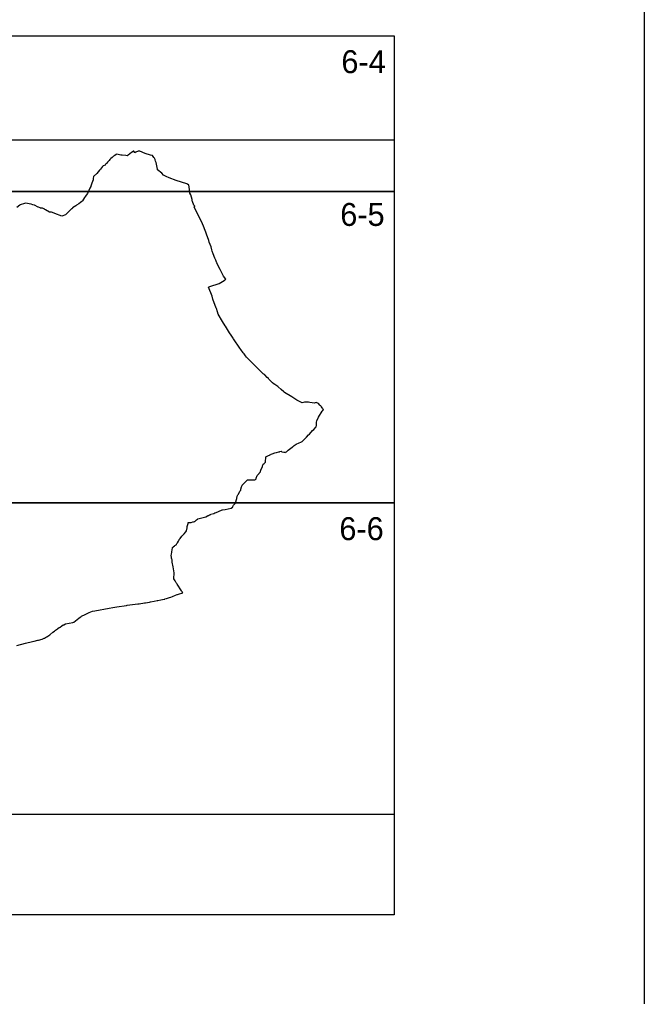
# Model space of a CAD drawing. Extents: x -447352 to -425530, y -1135906 to -1121091.
# Drawn here: x -429213.6 to -428963, y -1126703.7 to -1126311.8 of the extents above; entities that cross this region are included whole.
import ezdxf

# ---------------------------------------------------------------- set-up
doc = ezdxf.new("R2010")
doc.units = 0
for name, color, linetype in [('Vrstva 1', 7, 'Continuous'), ('Vrstva 10', 7, 'Continuous'), ('Vrstva 4', 7, 'Continuous')]:
    doc.layers.add(name, color=color, linetype=linetype)

msp = doc.modelspace()

# ---------------------------------------------------------------- linework, layer by layer
at = {"layer": 'Vrstva 1'}
msp.add_lwpolyline([(-430447.95, -1126056.63), (-430447.95, -1127106.63), (-428962.95, -1127106.63), (-428962.95, -1126056.63)], close=True, dxfattribs=at)
msp.add_lwpolyline([(-429214.66, -1126562.92), (-429211.12, -1126562.05), (-429208.35, -1126561.37), (-429207.68, -1126561.16), (-429206.19, -1126560.81), (-429205.98, -1126560.75), (-429204.55, -1126560.35), (-429203.95, -1126560.09), (-429203.73, -1126560), (-429203.57, -1126559.93), (-429202.75, -1126559.48), (-429202.69, -1126559.44), (-429201.38, -1126558.67), (-429200.23, -1126557.62), (-429199.58, -1126557.11), (-429199.45, -1126557), (-429199.43, -1126556.99), (-429199.27, -1126556.87), (-429199.12, -1126556.76), (-429198.32, -1126556.2), (-429198.26, -1126556.16), (-429198.19, -1126556.11), (-429197.68, -1126555.76), (-429197.31, -1126555.5), (-429196.65, -1126555.04), (-429196.06, -1126554.63), (-429195.9, -1126554.66), (-429195.89, -1126554.66), (-429195.87, -1126554.65), (-429195.14, -1126554.25), (-429192.18, -1126553.67), (-429191.76, -1126553.53), (-429189.73, -1126551.9), (-429189.26, -1126551.56), (-429189.23, -1126551.54), (-429188.87, -1126551.28), (-429188.69, -1126551.15), (-429187.3, -1126550.45), (-429185.89, -1126549.81), (-429185.59, -1126549.66), (-429184.33, -1126549.2), (-429183.33, -1126548.96), (-429177.62, -1126547.9), (-429176.2, -1126547.63), (-429174.49, -1126547.38), (-429170.62, -1126546.82), (-429170.38, -1126546.79), (-429166.08, -1126546.26), (-429165.55, -1126546.2), (-429163.4, -1126545.85), (-429163.08, -1126545.79), (-429161.42, -1126545.52), (-429161.02, -1126545.46), (-429159.61, -1126545.16), (-429158.32, -1126544.89), (-429158.11, -1126544.85), (-429156.94, -1126544.63), (-429156.27, -1126544.5), (-429156.25, -1126544.49), (-429155.34, -1126544.28), (-429155.27, -1126544.26), (-429154.62, -1126544.11), (-429154.27, -1126543.99), (-429153.38, -1126543.7), (-429152.94, -1126543.56), (-429152.29, -1126543.31), (-429152.17, -1126543.27), (-429151.08, -1126542.78), (-429151.08, -1126542.78), (-429150.96, -1126542.74), (-429150.31, -1126542.51), (-429150.22, -1126542.48), (-429149.79, -1126542.33), (-429148.13, -1126541.75), (-429148.15, -1126541.69), (-429148.26, -1126541.52), (-429148.42, -1126541.3), (-429148.64, -1126540.97), (-429150.34, -1126538.33), (-429150.55, -1126537.99), (-429150.72, -1126537.72), (-429151.16, -1126537), (-429151.69, -1126536.15), (-429151.53, -1126533.79), (-429151.52, -1126533.7), (-429151.91, -1126531.41), (-429151.91, -1126531.39), (-429151.92, -1126531.36), (-429151.92, -1126531.36), (-429151.92, -1126531.33), (-429152.33, -1126529.5), (-429152.34, -1126529.31), (-429152.4, -1126528.51), (-429152.5, -1126528.23), (-429152.51, -1126528.21), (-429152.62, -1126528), (-429152.66, -1126527.92), (-429152.67, -1126527.54), (-429152.7, -1126526.84), (-429152.65, -1126526.34), (-429152.65, -1126526.33), (-429152.56, -1126525.46), (-429152.54, -1126525.36), (-429152.25, -1126523.71), (-429152.17, -1126523.63), (-429151.87, -1126523.29), (-429151.81, -1126523.22), (-429151.55, -1126523.1), (-429151.49, -1126523.05), (-429151.23, -1126522.84), (-429151, -1126522.67), (-429150.79, -1126522.51), (-429150.73, -1126522.47), (-429150.65, -1126522.33), (-429150.57, -1126522.22), (-429150.46, -1126522.05), (-429150.24, -1126521.72), (-429149.82, -1126521.06), (-429149.69, -1126520.81), (-429149.68, -1126520.8), (-429149.54, -1126520.51), (-429149.49, -1126520.43), (-429149.31, -1126520.09), (-429149.17, -1126519.95), (-429148.87, -1126519.63), (-429148.7, -1126519.45), (-429148.42, -1126519.1), (-429148.29, -1126518.94), (-429147.6, -1126518.08), (-429146.94, -1126517.27), (-429146.65, -1126516.91), (-429146.41, -1126515.74), (-429146.35, -1126515.51), (-429146.28, -1126515.23), (-429145.96, -1126513.93), (-429145.88, -1126513.64), (-429145.88, -1126513.61), (-429145.86, -1126513.56), (-429145.7, -1126513.55), (-429145.68, -1126513.55), (-429145.44, -1126513.55), (-429144.75, -1126513.53), (-429144.74, -1126513.53), (-429144.71, -1126513.53), (-429144.03, -1126513.35), (-429143.83, -1126513.3), (-429143.41, -1126513.19), (-429143.39, -1126513.17), (-429143.33, -1126513.11), (-429143.03, -1126512.84), (-429142.91, -1126512.75), (-429142.57, -1126512.49), (-429142.15, -1126512.17), (-429142.08, -1126512.16), (-429141.52, -1126512), (-429138.82, -1126511.23), (-429138.23, -1126510.96), (-429137.9, -1126510.81), (-429137.85, -1126510.79), (-429137.75, -1126510.74), (-429137.39, -1126510.55), (-429137.34, -1126510.53), (-429137.31, -1126510.52), (-429137.3, -1126510.51), (-429137.27, -1126510.49), (-429136.96, -1126510.34), (-429136.9, -1126510.31), (-429136.79, -1126510.26), (-429135.71, -1126509.92), (-429135.28, -1126509.74), (-429134.76, -1126509.52), (-429133.75, -1126509.11), (-429132.33, -1126508.48), (-429132.19, -1126508.47), (-429131.06, -1126508.42), (-429128.66, -1126507.86), (-429128.13, -1126507.47), (-429128.06, -1126507.34), (-429127.97, -1126507.17), (-429127.71, -1126506.66), (-429127.36, -1126506.22), (-429127.34, -1126506.2), (-429127.13, -1126505.91), (-429127.02, -1126505.74), (-429127.01, -1126505.73), (-429126.47, -1126503.95), (-429126.46, -1126503.93), (-429126.26, -1126502.97), (-429126, -1126502.51), (-429125.81, -1126502.18), (-429125.26, -1126501.06), (-429124.88, -1126500.55), (-429124.85, -1126500.42), (-429124.78, -1126500.12), (-429124.75, -1126499.98), (-429124.69, -1126499.73), (-429124.67, -1126499.63), (-429124.35, -1126498.62), (-429124.34, -1126498.61), (-429124.05, -1126498.34), (-429123.39, -1126497.7), (-429123.34, -1126497.66), (-429122.87, -1126497.18), (-429122.61, -1126496.91), (-429122.51, -1126496.8), (-429122.14, -1126496.49), (-429122.1, -1126496.49), (-429122.09, -1126496.49), (-429121.68, -1126496.48), (-429121.51, -1126496.48), (-429120.88, -1126496.5), (-429120.17, -1126496.5), (-429119.2, -1126496.41), (-429119.17, -1126496.41), (-429118.92, -1126496.38), (-429118.7, -1126496.02), (-429118.65, -1126495.89), (-429118.63, -1126495.84), (-429118.61, -1126495.78), (-429118.25, -1126494.76), (-429118.11, -1126494.6), (-429118.01, -1126494.48), (-429117.97, -1126494.44), (-429117.91, -1126494.36), (-429117.79, -1126494.23), (-429117.52, -1126493.92), (-429117.43, -1126493.81), (-429117.33, -1126493.69), (-429116.99, -1126493.3), (-429116.92, -1126492.92), (-429116.86, -1126492.6), (-429116.79, -1126492.47), (-429116.24, -1126491.55), (-429116.13, -1126491.16), (-429115.94, -1126490.46), (-429115.82, -1126490.17), (-429115.53, -1126489.91), (-429114.98, -1126489.4), (-429114.91, -1126489.33), (-429114.81, -1126487.22), (-429113.79, -1126486.74), (-429113.39, -1126486.53), (-429113.14, -1126486.39), (-429112.85, -1126486.24), (-429112.63, -1126486.16), (-429112.29, -1126486.03), (-429112.24, -1126486.01), (-429111.15, -1126485.6), (-429111.14, -1126485.6), (-429110.65, -1126485.54), (-429110.57, -1126485.52), (-429109.54, -1126485.26), (-429109.39, -1126485.22), (-429109.3, -1126485.19), (-429109.13, -1126485.14), (-429108.6, -1126484.97), (-429108.6, -1126484.97), (-429108.59, -1126484.98), (-429108.59, -1126484.99), (-429108.56, -1126485.04), (-429108.43, -1126485.26), (-429107.55, -1126485.36), (-429107.35, -1126485.38), (-429106.99, -1126485.42), (-429106.9, -1126485.38), (-429106.47, -1126485.2), (-429105.82, -1126484.49), (-429104.18, -1126483.33), (-429104.09, -1126483.27), (-429103.92, -1126483.15), (-429103.41, -1126482.74), (-429102.66, -1126482.13), (-429101.39, -1126481.57), (-429100.77, -1126481.29), (-429100.23, -1126481.05), (-429100.17, -1126481.02), (-429098.52, -1126479.35), (-429097.68, -1126478.46), (-429097.32, -1126478.09), (-429096.13, -1126476.72), (-429095.53, -1126476.27), (-429095.48, -1126476.22), (-429094.64, -1126475.21), (-429094.44, -1126474.64), (-429094.53, -1126473.31), (-429094.31, -1126472.82), (-429093.67, -1126471.37), (-429092.21, -1126468.89), (-429092.18, -1126468.84), (-429092.18, -1126468.84), (-429092.16, -1126468.82), (-429092.13, -1126468.78), (-429091.98, -1126468.58), (-429091.72, -1126468.24), (-429091.98, -1126467.95), (-429092.12, -1126467.72), (-429092.59, -1126466.99), (-429092.79, -1126466.79), (-429092.94, -1126466.63), (-429093.13, -1126466.43), (-429093.71, -1126465.87), (-429094.56, -1126465.39), (-429095.01, -1126465.57), (-429095.34, -1126465.7), (-429097.09, -1126465.42), (-429097.7, -1126465.33), (-429097.84, -1126465.32), (-429098.43, -1126465.31), (-429098.81, -1126465.25), (-429098.97, -1126465.23), (-429099.01, -1126465.22), (-429099.04, -1126465.22), (-429099.04, -1126465.22), (-429099.07, -1126465.22), (-429099.17, -1126465.25), (-429099.3, -1126465.29), (-429100.2, -1126465.52), (-429100.27, -1126465.49), (-429102.34, -1126464.45), (-429104.36, -1126463.18), (-429107.27, -1126461.35), (-429107.43, -1126461.22), (-429107.47, -1126461.18), (-429107.56, -1126461.1), (-429108.7, -1126460.17), (-429109.85, -1126459.13), (-429109.96, -1126459.02), (-429111.17, -1126458.26), (-429111.45, -1126458.04), (-429112.08, -1126457.54), (-429112.39, -1126457.29), (-429112.89, -1126456.76), (-429113.61, -1126456), (-429113.76, -1126455.84), (-429114.22, -1126455.35), (-429115.19, -1126454.32), (-429115.39, -1126454.22), (-429115.39, -1126454.22), (-429115.57, -1126454.12), (-429115.77, -1126454.02), (-429116.6, -1126453.19), (-429117.23, -1126452.57), (-429118.41, -1126451.39), (-429119.34, -1126450.46), (-429119.5, -1126450.3), (-429119.94, -1126449.85), (-429120.18, -1126449.61), (-429120.27, -1126449.52), (-429120.31, -1126449.48), (-429120.83, -1126448.96), (-429121.47, -1126448.31), (-429121.55, -1126448.23), (-429121.57, -1126448.21), (-429121.72, -1126448.06), (-429122.55, -1126447.22), (-429122.93, -1126446.72), (-429123.21, -1126446.35), (-429123.53, -1126445.92), (-429123.89, -1126445.44), (-429124.84, -1126444.18), (-429125.21, -1126443.64), (-429127.75, -1126439.9), (-429127.92, -1126439.64), (-429128.69, -1126438.46), (-429129.36, -1126437.44), (-429130.2, -1126436.12), (-429131, -1126434.84), (-429131.08, -1126434.71), (-429132.17, -1126432.86), (-429133.85, -1126430.01), (-429133.85, -1126430.01), (-429133.85, -1126430.01), (-429133.86, -1126430), (-429134.19, -1126429.03), (-429134.64, -1126427.72), (-429134.7, -1126427.52), (-429136.08, -1126424.01), (-429136.37, -1126422.76), (-429137.85, -1126419.09), (-429137.22, -1126418.89), (-429133.5, -1126417.64), (-429131.53, -1126416.42), (-429131.35, -1126416.31), (-429131.29, -1126416.28), (-429131.09, -1126416.15), (-429130.82, -1126415.99), (-429131.74, -1126414.79), (-429133.15, -1126412.01), (-429133.9, -1126410.55), (-429134.43, -1126409.38), (-429134.45, -1126409.35), (-429134.51, -1126409.21), (-429134.52, -1126409.18), (-429134.54, -1126409.15), (-429134.58, -1126409.06), (-429134.91, -1126408.34), (-429135.23, -1126407.54), (-429135.94, -1126405.77), (-429136.35, -1126404.74), (-429136.5, -1126404.11), (-429136.76, -1126402.97), (-429137.5, -1126401.08), (-429137.7, -1126400.48), (-429138.64, -1126397.86), (-429138.91, -1126397.13), (-429140.1, -1126394.05), (-429140.17, -1126393.86), (-429140.2, -1126393.79), (-429143.55, -1126386.97), (-429143.24, -1126386.84), (-429143.22, -1126386.82), (-429143.32, -1126386.65), (-429143.4, -1126386.55), (-429143.57, -1126386.32), (-429143.63, -1126386.25), (-429144.24, -1126384.76), (-429144.29, -1126384.47), (-429144.39, -1126384.01), (-429144.4, -1126383.95), (-429144.91, -1126382.12), (-429145.21, -1126381.48), (-429145.22, -1126381.41), (-429145.26, -1126381.05), (-429145.4, -1126379.96), (-429145.68, -1126378.12), (-429145.74, -1126378.1), (-429146.04, -1126378), (-429146.42, -1126377.73), (-429146.43, -1126377.73), (-429150.73, -1126376.32), (-429153.52, -1126375.34), (-429154.83, -1126374.72), (-429155.8, -1126374.17), (-429156.52, -1126373.38), (-429158.2, -1126372.11), (-429158.26, -1126371.81), (-429158.84, -1126369.11), (-429158.99, -1126368.57), (-429159.17, -1126368.06), (-429159.22, -1126367.9), (-429159.47, -1126367.39), (-429159.72, -1126367.07), (-429160.3, -1126366.38), (-429161.05, -1126366.17), (-429163.23, -1126365.51), (-429165.32, -1126364.55), (-429165.94, -1126364.56), (-429166.89, -1126364.92), (-429167.02, -1126365.02), (-429167.09, -1126365.06), (-429167.23, -1126365.16), (-429167.27, -1126365.19), (-429167.29, -1126365.17), (-429167.5, -1126364.92), (-429167.75, -1126364.64), (-429167.83, -1126364.54), (-429167.92, -1126364.59), (-429168.43, -1126364.98), (-429168.62, -1126365.12), (-429169.29, -1126365.64), (-429170.04, -1126366.2), (-429170.38, -1126366.42), (-429170.97, -1126366.38), (-429172.45, -1126366.23), (-429172.91, -1126366.14), (-429174.5, -1126365.82), (-429174.8, -1126365.94), (-429175.36, -1126366.28), (-429175.91, -1126366.6), (-429176.4, -1126367.06), (-429176.93, -1126367.55), (-429177.33, -1126367.94), (-429177.34, -1126367.95), (-429177.67, -1126368.29), (-429177.8, -1126368.43), (-429178.31, -1126368.98), (-429178.76, -1126369.53), (-429178.92, -1126369.72), (-429179.28, -1126370.15), (-429180.02, -1126370.48), (-429180.04, -1126370.49), (-429180.24, -1126370.73), (-429181.1, -1126371.75), (-429181.48, -1126372.21), (-429182.61, -1126373.56), (-429182.62, -1126373.57), (-429183.86, -1126374.75), (-429183.98, -1126375.58), (-429184.03, -1126375.95), (-429184.07, -1126376.05), (-429184.55, -1126377.4), (-429184.99, -1126378.64), (-429185.02, -1126378.72), (-429185.32, -1126379.42), (-429186.25, -1126381.59), (-429186.27, -1126381.6), (-429186.84, -1126382.29), (-429187.14, -1126382.63), (-429187.14, -1126382.64), (-429187.48, -1126383.18), (-429188.35, -1126384.57), (-429188.44, -1126384.71), (-429188.61, -1126384.84), (-429189.14, -1126385.23), (-429189.75, -1126385.68), (-429189.75, -1126385.68), (-429190.72, -1126386.31), (-429190.85, -1126386.41), (-429191.03, -1126386.53), (-429192.33, -1126387.38), (-429192.34, -1126387.39), (-429192.6, -1126387.66), (-429192.72, -1126387.78), (-429192.94, -1126388), (-429193.22, -1126388.28), (-429193.79, -1126388.85), (-429194.95, -1126390.02), (-429195.15, -1126390.1), (-429196.65, -1126390.67), (-429199.46, -1126389.55), (-429199.46, -1126389.55), (-429199.47, -1126389.57), (-429200.38, -1126389.19), (-429200.69, -1126389.06), (-429200.71, -1126389.06), (-429201.1, -1126389.06), (-429201.58, -1126389.06), (-429203.14, -1126388.08), (-429203.4, -1126387.94), (-429203.69, -1126387.78), (-429203.75, -1126387.75), (-429203.79, -1126387.74), (-429204.33, -1126387.51), (-429204.38, -1126387.5), (-429204.39, -1126387.5), (-429204.54, -1126387.49), (-429204.66, -1126387.48), (-429204.97, -1126387.47), (-429204.99, -1126387.47), (-429204.99, -1126387.47), (-429205.1, -1126387.42), (-429205.34, -1126387.32), (-429205.94, -1126387.07), (-429206.1, -1126387.01), (-429207.62, -1126386.28), (-429208.24, -1126386.1), (-429208.91, -1126385.9), (-429211.23, -1126385.46), (-429211.24, -1126385.46), (-429211.64, -1126385.58), (-429213.38, -1126386.15), (-429213.51, -1126386.26), (-429214.72, -1126387.22)], dxfattribs=at)
at = {"layer": 'Vrstva 10'}
msp.add_lwpolyline([(-429063.36, -1126360.06), (-429063.36, -1126671.03), (-429396.23, -1126671.03), (-429396.23, -1126505.74), (-429375.86, -1126505.74), (-429375.86, -1126380.74), (-429375.86, -1126360.06), (-429063.36, -1126360.06)], dxfattribs=at)
at = {"layer": 'Vrstva 4'}
msp.add_line((-429375.86, -1126318.24), (-429063.36, -1126318.24), dxfattribs=at)
msp.add_lwpolyline([(-429063.36, -1126318.24), (-429063.36, -1126380.74), (-429219.61, -1126380.74), (-429219.61, -1126318.24)], dxfattribs=at)
for points in [[(-429063.36, -1126380.74), (-429063.36, -1126505.74), (-429219.61, -1126505.74), (-429219.61, -1126380.74)], [(-429063.36, -1126505.74), (-429063.36, -1126630.74), (-429219.61, -1126630.74), (-429219.61, -1126505.74)]]:
    msp.add_lwpolyline(points, close=True, dxfattribs=at)

# ---------------------------------------------------------------- texts
at = {"layer": 'Vrstva 1'}
for s, p in [('6-4', (-429084.49, -1126333.28)), ('6-5', (-429084.94, -1126394.57)), ('6-6', (-429085.31, -1126520.64))]:
    msp.add_text(s, height=9.2, dxfattribs=at).set_placement(p)

doc.saveas('drawing.dxf')
